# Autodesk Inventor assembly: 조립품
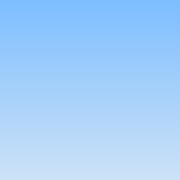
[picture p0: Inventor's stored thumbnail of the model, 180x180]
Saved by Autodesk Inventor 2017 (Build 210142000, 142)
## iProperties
Part Number: 조립품
Material: 일반
Document SubType Name: Assembly
Designer: user
Author: user
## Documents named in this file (1)
- C:\Users\user\Desktop\710606V1043\조립품.iam
